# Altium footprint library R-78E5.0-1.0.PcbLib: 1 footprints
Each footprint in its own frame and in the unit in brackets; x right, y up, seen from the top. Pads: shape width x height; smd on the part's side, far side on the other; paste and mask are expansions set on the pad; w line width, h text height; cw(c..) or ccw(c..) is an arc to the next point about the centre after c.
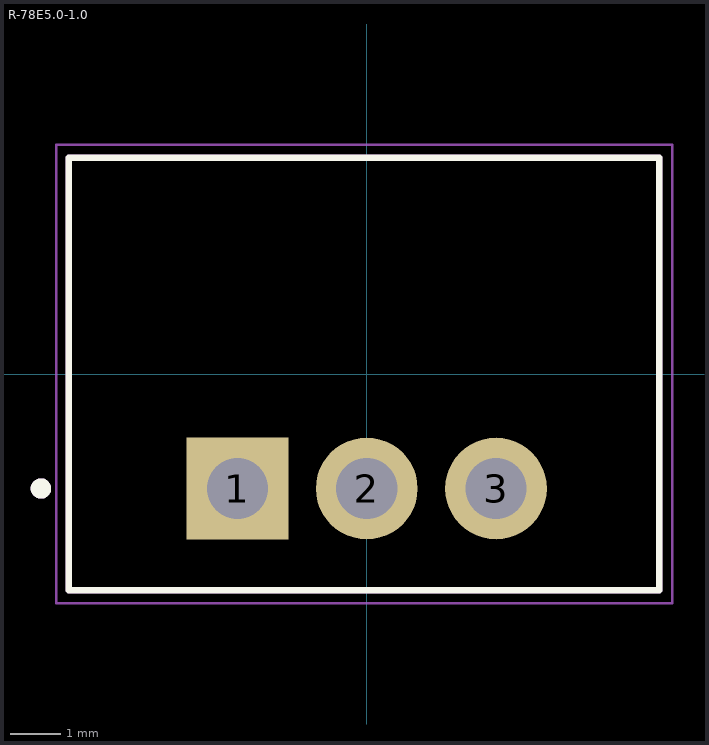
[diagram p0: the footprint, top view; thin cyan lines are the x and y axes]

## R-78E5.0-1.0 [mm]
pads (3):
  rect 2x2 hole 1.2: 1(-2.54,-2.25)
  round 2 hole 1.2: 2(0,-2.25) 3(2.54,-2.25)
Top Overlay:
  circle w0.2: c-6.4,-2.25 r0.1
  lines w0.127: -5.85,-4.25 5.75,-4.25 5.75,4.25 -5.85,4.25 -5.85,-4.25
Mechanical 13:
  circle w0.2: c-6.4,-2.25 r0.1
  lines w0.127: -5.85,-4.25 5.75,-4.25 5.75,4.25 -5.85,4.25 -5.85,-4.25
Mechanical 15:
  lines w0.05: -6.1,-4.5 6,-4.5 6,4.5 -6.1,4.5 -6.1,-4.5
3D body "R-78E5.0-1.0.STEP": height 10.41, standoff -4.09, extent -5.8,-4.309 5.8,4.191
